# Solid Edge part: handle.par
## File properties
Document Number: DOC NUMBER
Revision: REV NUMBER
Project Name: COFFEE MAKER
Title: HANDLE
Subject: COFFEE MAKER
Author: rkriggs
Keywords: HANDLE
Comments: COMMENTS FIELD
Template: Normal.par
Last saved by: plm
Revision: 52
Application: Solid Edge
Category: COFFEE MAKER
Manager: MANAGER FIELD
Company: UGS
CUSTOM NAME FIELD: CUSTOM VALUE FIELD
Density: 913.000 kg/m^3
Accuracy: 0.99
圖檔名稱: handle
圖檔編號: handle
major_rev: A
classification: Mechanical/Part
generation: 2
id: A4CE777A2267413E8DB3EA348D77EABB
thumbnail: vault:///?fileId=16E32DA9843144A487A99971918B115D
authoring_tool: Solid Edge
Material: Polypropylene, general purpose
Face Style: White
Fill Style: ANSI34(Plastic)
Virtual Style: Green (Shiny)
Coef. of Thermal Exp: 6.8e-05
Thermal Conductivity: 2.1
Specific Heat: 1884.0
Modulus of Elasticity: 1103161120.0
Poisson's Ratio: 0.35
Yield Stress: 33094833.6
Ultimate Stress: 0.0
Elongation: 0.0
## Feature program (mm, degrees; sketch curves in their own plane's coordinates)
pattern "unnamed Pattern 1"
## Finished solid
Body 1: solid body, 87 faces, 208 edges, 122 vertices.
  Faces by surface: blend 37, cylinder 21, plane 19, offset 4, spline 3, sphere 2, torus 1
  Edges by curve: intersection 67, line 48, circle 47, ellipse 34, curve on surface 12
Bounding box of the edges (mm; curved faces can reach further): 40.285 x 21.790 x 76.838, from (-27.0453, 0.2216, -54.6278) to (13.2402, 22.0111, 22.2099).
Cylindrical faces by radius (mm): R1.27 x12, R1.5875 x1, R2.54 x4, R57.15 x1, R73.406 x1, R74.676 x1, R76.2 x1
Toroidal faces (ring radius, tube radius in mm): R72.136 r1.27 x1
Spherical faces by radius (mm): R1.27 x2
Planar faces by outward normal: +x 3, +y 2, -x 1, -y 2, -z 2, oblique 9
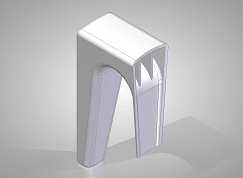
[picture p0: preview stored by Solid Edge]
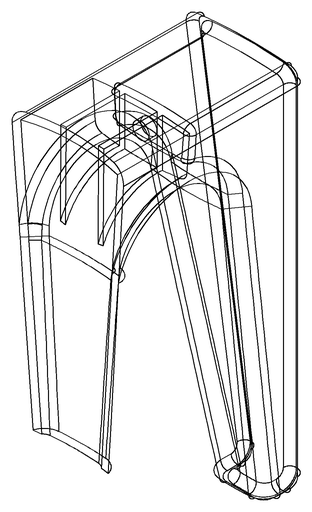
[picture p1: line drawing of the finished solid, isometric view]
